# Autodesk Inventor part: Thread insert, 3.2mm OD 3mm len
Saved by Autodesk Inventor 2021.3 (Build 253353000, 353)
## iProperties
Created: 2022-07
Part Number: Thread insert, 3.2mm OD 3mm len
Material: Generic
Document SubType Name: Modeling
Designer: Administrator
Density: 1 g/cm^3
Appearance: Default
Title: Thread insert, 3.2mm OD 3mm len
Author: Administrator
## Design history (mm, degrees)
feature "Body1"
body "Solid1"
